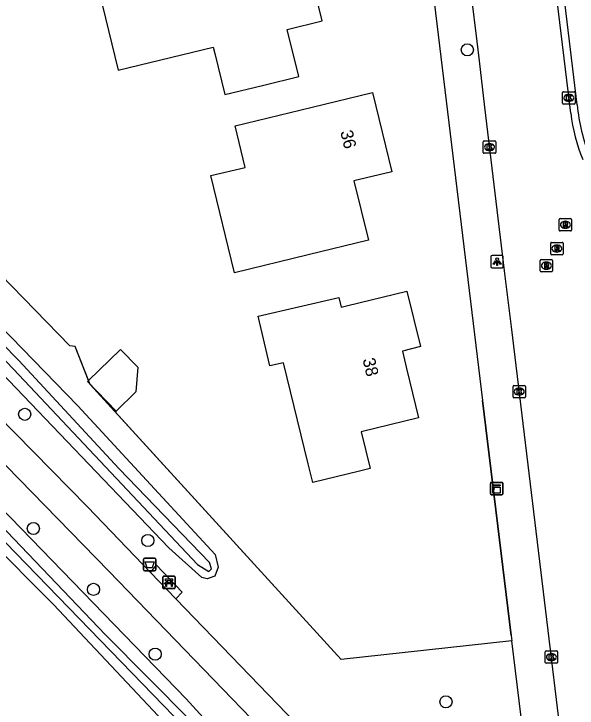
# Model space of a CAD drawing. Extents: x 157663 to 158496, y 379212 to 380934.
# Drawn here: x 158046.6 to 158091.9, y 380411.1 to 380467 of the extents above; entities that cross this region are included whole.
import ezdxf

# ---------------------------------------------------------------- set-up
doc = ezdxf.new("R2010")
doc.units = 0
for name, color, linetype in [('IMGEO_Afvalbak', 7, 'Continuous'), ('IMGEO_Bank', 7, 'Continuous'), ('IMGEO_Boom', 7, 'Continuous'), ('IMGEO_Groenvoorziening', 7, 'Continuous'), ('IMGEO_Hek', 7, 'Continuous'), ('IMGEO_Kast', 7, 'Continuous'), ('IMGEO_Kolk', 7, 'Continuous'), ('IMGEO_Lichtpunt', 7, 'Continuous'), ('IMGEO_Muur', 7, 'Continuous'), ('IMGEO_Pand', 7, 'Continuous'), ('IMGEO_Pand_nummerreeks', 7, 'Continuous'), ('IMGEO_Rijbaan_lokaal_open', 7, 'Continuous'), ('IMGEO_Rioolput', 7, 'Continuous'), ('IMGEO_Voetpad_open', 7, 'Continuous'), ('IMGEO_Waterloop', 7, 'Continuous')]:
    doc.layers.add(name, color=color, linetype=linetype)

msp = doc.modelspace()

# ---------------------------------------------------------------- linework, layer by layer
at = {"layer": 'IMGEO_Afvalbak'}
for p, q in [((158057.124, 380423.14), (158057.914, 380423.14)), ((158057.914, 380423.14), (158057.124, 380423.14)), ((158057.024, 380422.24), (158057.024, 380423.04)), ((158057.024, 380423.04), (158057.024, 380422.24)), ((158058.014, 380423.04), (158058.014, 380422.24)), ((158058.014, 380422.24), (158058.014, 380423.04)), ((158057.914, 380422.14), (158057.124, 380422.14)), ((158057.124, 380422.14), (158057.914, 380422.14))]:
    msp.add_line(p, q, dxfattribs=at)
msp.add_lwpolyline([(158057.167, 380422.854), (158057.871, 380422.854), (158057.722, 380422.384), (158057.316, 380422.384), (158057.167, 380422.854)], dxfattribs=at)
for centre, start, end in [((158057.124, 380423.04), 90, 180), ((158057.124, 380423.04), 90, 180), ((158057.914, 380423.04), 0, 90), ((158057.914, 380423.04), 360, 90), ((158057.124, 380422.24), 180, 270), ((158057.124, 380422.24), 180, 270), ((158057.914, 380422.24), 270, 0), ((158057.914, 380422.24), 270, 0)]:
    msp.add_arc(centre, 0.1, start, end, dxfattribs=at)
at = {"layer": 'IMGEO_Bank'}
for p, q in [((158058.579, 380420.771), (158058.579, 380421.612)), ((158058.579, 380421.612), (158058.579, 380420.771)), ((158058.654, 380421.696), (158059.495, 380421.696)), ((158059.495, 380421.696), (158058.654, 380421.696)), ((158059.579, 380421.621), (158059.579, 380420.78)), ((158059.579, 380420.78), (158059.579, 380421.621)), ((158059.276, 380421.094), (158058.883, 380421.094)), ((158058.888, 380421.202), (158058.888, 380421.308)), ((158058.932, 380421.308), (158058.932, 380421.202)), ((158059.22, 380421.314), (158058.938, 380421.314)), ((158058.938, 380421.196), (158059.22, 380421.196)), ((158059.226, 380421.202), (158059.226, 380421.308)), ((158059.27, 380421.308), (158059.27, 380421.202)), ((158059.504, 380420.696), (158058.663, 380420.696)), ((158058.663, 380420.696), (158059.504, 380420.696))]:
    msp.add_line(p, q, dxfattribs=at)
for points in [[(158058.882, 380421.314), (158058.796, 380421.314), (158058.796, 380421.475), (158059.359, 380421.475), (158059.359, 380421.314), (158059.276, 380421.314)], [(158058.826, 380421.094), (158058.684, 380421.094), (158058.796, 380421.196), (158058.882, 380421.196)], [(158058.876, 380421.087), (158058.876, 380420.88), (158058.833, 380420.88), (158058.833, 380421.087)], [(158059.276, 380421.196), (158059.359, 380421.196), (158059.471, 380421.094), (158059.332, 380421.094)], [(158059.326, 380421.087), (158059.326, 380420.88), (158059.282, 380420.88), (158059.282, 380421.087)]]:
    msp.add_lwpolyline(points, dxfattribs=at)
for centre, radius, start, end in [((158058.657, 380421.618), 0.0779, 92.4484, 184.2845), ((158058.657, 380421.618), 0.0779, 92.4484, 184.2845), ((158059.501, 380421.618), 0.0779, 2.4484, 94.2845), ((158059.501, 380421.618), 0.0779, 2.4484, 94.2845), ((158058.826, 380421.087), 0.00671, 2.8957, 87.1043), ((158058.883, 380421.087), 0.00671, 92.8957, 177.1043), ((158058.881, 380421.307), 0.00671, 2.8957, 87.1043), ((158058.881, 380421.203), 0.00671, 272.8957, 357.1043), ((158058.938, 380421.307), 0.00671, 92.8957, 177.1043), ((158058.938, 380421.203), 0.00671, 182.8957, 267.1043), ((158059.22, 380421.307), 0.00671, 2.8957, 87.1043), ((158059.22, 380421.203), 0.00671, 272.8957, 357.1043), ((158059.277, 380421.307), 0.00671, 92.8957, 177.1043), ((158059.277, 380421.203), 0.00671, 182.8957, 267.1043), ((158059.275, 380421.087), 0.00671, 2.8957, 87.1043), ((158059.332, 380421.087), 0.00671, 92.8957, 177.1043), ((158058.657, 380420.774), 0.0779, 182.4484, 274.2845), ((158058.657, 380420.774), 0.0779, 182.4484, 274.2845), ((158059.501, 380420.774), 0.0779, 272.4484, 4.2845), ((158059.501, 380420.774), 0.0779, 272.4484, 4.2845)]:
    msp.add_arc(centre, radius, start, end, dxfattribs=at)
at = {"layer": 'IMGEO_Boom'}
for centre in [(158083.093, 380464.08), (158047.463, 380434.732), (158048.159, 380425.543), (158057.379, 380424.579), (158053.003, 380420.637), (158057.961, 380415.427), (158081.373, 380411.578)]:
    msp.add_circle(centre, 0.489, dxfattribs=at)
at = {"layer": 'IMGEO_Groenvoorziening'}
for points in [[(158051.734, 380435.421), (158062.804, 380423.435), (158063.034, 380422.418), (158062.773, 380421.709), (158062.142, 380421.478), (158061.715, 380421.586), (158059.072, 380423.978), (158035.643, 380448.459), (158025.607, 380458.749), (158024.421, 380460.97), (158024.539, 380461.599), (158024.891, 380461.928), (158025.703, 380461.837), (158026.714, 380461.388), (158035.627, 380451.982), (158051.734, 380435.421)], [(158021.901, 380448.106), (158021.75, 380448.847), (158021.75, 380449.873), (158021.907, 380450.575), (158022.246, 380450.981), (158022.582, 380450.916), (158024.971, 380448.209), (158041.314, 380431.54), (158060.467, 380411.817), (158064.837, 380407.009)], [(158052.599, 380437.464), (158051.524, 380440.195), (158051.082, 380440.247), (158042.683, 380448.851), (158042.449, 380449.52)], [(158021.901, 380448.106), (158022.644, 380447.175), (158033.581, 380435.679), (158049.766, 380419.415), (158061.595, 380406.859), (158064.13, 380404.829), (158064.886, 380404.754), (158065.351, 380405.014), (158065.528, 380405.554), (158064.837, 380407.009)], [(158086.681, 380416.507), (158072.931, 380414.996), (158054.747, 380434.921), (158054.814, 380434.985)]]:
    msp.add_lwpolyline(points, dxfattribs=at)
at = {"layer": 'IMGEO_Hek'}
msp.add_lwpolyline([(158086.631, 380416.924), (158084.325, 380435.852)], dxfattribs=at)
at = {"layer": 'IMGEO_Kast'}
for p, q in [((158084.951, 380428.33), (158084.951, 380429.171)), ((158084.951, 380429.171), (158084.951, 380428.33)), ((158085.026, 380429.255), (158085.867, 380429.255)), ((158085.867, 380429.255), (158085.026, 380429.255)), ((158085.951, 380429.18), (158085.951, 380428.339)), ((158085.951, 380428.339), (158085.951, 380429.18)), ((158085.876, 380428.255), (158085.035, 380428.255)), ((158085.035, 380428.255), (158085.876, 380428.255))]:
    msp.add_line(p, q, dxfattribs=at)
for points in [[(158085.146, 380429.045), (158085.746, 380429.045), (158085.746, 380428.96), (158085.146, 380428.96), (158085.146, 380429.045)], [(158085.146, 380428.87), (158085.746, 380428.87), (158085.746, 380428.381), (158085.146, 380428.381), (158085.146, 380428.87)]]:
    msp.add_lwpolyline(points, dxfattribs=at)
msp.add_circle((158085.23, 380428.719), 0.0377, dxfattribs=at)
for centre, start, end in [((158085.029, 380429.177), 92.4484, 184.2845), ((158085.029, 380429.177), 92.4484, 184.2845), ((158085.873, 380429.177), 2.4484, 94.2845), ((158085.873, 380429.177), 2.4484, 94.2845), ((158085.029, 380428.333), 182.4484, 274.2845), ((158085.029, 380428.333), 182.4484, 274.2845), ((158085.873, 380428.333), 272.4484, 4.2845), ((158085.873, 380428.333), 272.4484, 4.2845)]:
    msp.add_arc(centre, 0.0779, start, end, dxfattribs=at)
at = {"layer": 'IMGEO_Kolk'}
for p, q in [((158090.762, 380459.776), (158090.762, 380460.628)), ((158090.837, 380460.702), (158091.689, 380460.702)), ((158091.763, 380460.628), (158091.763, 380459.776)), ((158091.25, 380460.482), (158091.275, 380460.482)), ((158091.689, 380459.702), (158090.837, 380459.702)), ((158091.273, 380459.922), (158091.248, 380459.922)), ((158084.378, 380455.82), (158084.378, 380456.672)), ((158084.453, 380456.746), (158085.305, 380456.746)), ((158085.379, 380456.672), (158085.379, 380455.82)), ((158084.866, 380456.526), (158084.891, 380456.526)), ((158085.305, 380455.746), (158084.453, 380455.746)), ((158084.889, 380455.966), (158084.864, 380455.966)), ((158086.772, 380436.131), (158086.772, 380436.983)), ((158086.847, 380437.057), (158087.699, 380437.057)), ((158087.26, 380436.837), (158087.285, 380436.837)), ((158087.773, 380436.983), (158087.773, 380436.131)), ((158087.699, 380436.057), (158086.847, 380436.057)), ((158087.283, 380436.277), (158087.258, 380436.277)), ((158089.361, 380414.763), (158089.361, 380415.615)), ((158089.436, 380415.689), (158090.288, 380415.689)), ((158089.849, 380415.469), (158089.874, 380415.469)), ((158090.362, 380415.615), (158090.362, 380414.763)), ((158089.872, 380414.909), (158089.847, 380414.909)), ((158090.288, 380414.689), (158089.436, 380414.689))]:
    msp.add_line(p, q, dxfattribs=at)
for points in [[(158090.762, 380459.776), (158090.762, 380460.628)], [(158090.837, 380460.702), (158091.689, 380460.702)], [(158091.763, 380460.628), (158091.763, 380459.776)], [(158091.083, 380460.402), (158091.206, 380460.402), (158091.206, 380460.251), (158091.336, 380460.402), (158091.5, 380460.402), (158091.354, 380460.251), (158091.507, 380460.002), (158091.355, 380460.002), (158091.27, 380460.166), (158091.206, 380460.099), (158091.206, 380460.002), (158091.083, 380460.002), (158091.083, 380460.402)], [(158091.689, 380459.702), (158090.837, 380459.702)], [(158084.378, 380455.82), (158084.378, 380456.672)], [(158084.453, 380456.746), (158085.305, 380456.746)], [(158085.379, 380456.672), (158085.379, 380455.82)], [(158084.699, 380456.446), (158084.822, 380456.446), (158084.822, 380456.295), (158084.952, 380456.446), (158085.116, 380456.446), (158084.97, 380456.295), (158085.123, 380456.046), (158084.971, 380456.046), (158084.886, 380456.21), (158084.822, 380456.143), (158084.822, 380456.046), (158084.699, 380456.046), (158084.699, 380456.446)], [(158085.305, 380455.746), (158084.453, 380455.746)], [(158086.772, 380436.131), (158086.772, 380436.983)], [(158086.847, 380437.057), (158087.699, 380437.057)], [(158087.093, 380436.757), (158087.216, 380436.757), (158087.216, 380436.606), (158087.346, 380436.757), (158087.51, 380436.757), (158087.364, 380436.606), (158087.517, 380436.357), (158087.365, 380436.357), (158087.28, 380436.521), (158087.216, 380436.454), (158087.216, 380436.357), (158087.093, 380436.357), (158087.093, 380436.757)], [(158087.773, 380436.983), (158087.773, 380436.131)], [(158087.699, 380436.057), (158086.847, 380436.057)], [(158089.361, 380414.763), (158089.361, 380415.615)], [(158089.436, 380415.689), (158090.288, 380415.689)], [(158089.682, 380415.389), (158089.805, 380415.389), (158089.805, 380415.238), (158089.935, 380415.389), (158090.099, 380415.389), (158089.953, 380415.238), (158090.106, 380414.989), (158089.954, 380414.989), (158089.869, 380415.153), (158089.805, 380415.086), (158089.805, 380414.989), (158089.682, 380414.989), (158089.682, 380415.389)], [(158090.362, 380415.615), (158090.362, 380414.763)], [(158090.288, 380414.689), (158089.436, 380414.689)]]:
    msp.add_lwpolyline(points, dxfattribs=at)
for centre, start, end in [((158090.839, 380460.626), 91.552, 178.448), ((158090.839, 380460.626), 91.552, 178.448), ((158091.687, 380460.626), 1.552, 88.448), ((158091.687, 380460.626), 1.552, 88.448), ((158090.839, 380459.778), 181.552, 268.448), ((158090.839, 380459.778), 181.552, 268.448), ((158091.687, 380459.778), 271.552, 358.448), ((158091.687, 380459.778), 271.552, 358.448), ((158084.455, 380456.67), 91.552, 178.448), ((158084.455, 380456.67), 91.552, 178.448), ((158085.303, 380456.67), 1.552, 88.448), ((158085.303, 380456.67), 1.552, 88.448), ((158084.455, 380455.822), 181.552, 268.448), ((158084.455, 380455.822), 181.552, 268.448), ((158085.303, 380455.822), 271.552, 358.448), ((158085.303, 380455.822), 271.552, 358.448), ((158086.849, 380436.981), 91.552, 178.448), ((158086.849, 380436.981), 91.552, 178.448), ((158087.697, 380436.981), 1.552, 88.448), ((158087.697, 380436.981), 1.552, 88.448), ((158086.849, 380436.133), 181.552, 268.448), ((158086.849, 380436.133), 181.552, 268.448), ((158087.697, 380436.133), 271.552, 358.448), ((158087.697, 380436.133), 271.552, 358.448), ((158089.438, 380415.613), 91.552, 178.448), ((158089.438, 380415.613), 91.552, 178.448), ((158090.286, 380415.613), 1.552, 88.448), ((158090.286, 380415.613), 1.552, 88.448), ((158089.438, 380414.765), 181.552, 268.448), ((158089.438, 380414.765), 181.552, 268.448), ((158090.286, 380414.765), 271.552, 358.448), ((158090.286, 380414.765), 271.552, 358.448)]:
    msp.add_arc(centre, 0.0765, start, end, dxfattribs=at)
for centre, major_axis, ratio, start_param, end_param in [((158091.249, 380460.202), (-0.387, 0.002), 0.722429, 4.712389, 7.853982), ((158091.274, 380460.202), (-0.39, 0.002), 0.717154, 1.570796, 4.712389), ((158084.865, 380456.246), (-0.387, 0.002), 0.722429, 4.712389, 7.853982), ((158084.89, 380456.246), (-0.39, 0.002), 0.717154, 1.570796, 4.712389), ((158087.259, 380436.557), (-0.387, 0.002), 0.722429, 4.712389, 7.853982), ((158087.284, 380436.557), (-0.39, 0.002), 0.717154, 1.570796, 4.712389), ((158089.848, 380415.189), (-0.387, 0.002), 0.722429, 4.712389, 7.853982), ((158089.873, 380415.189), (-0.39, 0.002), 0.717154, 1.570796, 4.712389)]:
    msp.add_ellipse(centre, major_axis=major_axis, ratio=ratio, start_param=start_param, end_param=end_param, dxfattribs=at)
at = {"layer": 'IMGEO_Lichtpunt'}
for p, q in [((158084.994, 380447.425), (158084.994, 380446.618)), ((158084.994, 380447.425), (158084.994, 380446.618)), ((158085.896, 380447.52), (158085.088, 380447.52)), ((158085.896, 380447.52), (158085.088, 380447.52)), ((158085.99, 380446.618), (158085.99, 380447.425)), ((158085.99, 380446.618), (158085.99, 380447.425)), ((158085.088, 380446.524), (158085.896, 380446.524)), ((158085.088, 380446.524), (158085.896, 380446.524))]:
    msp.add_line(p, q, dxfattribs=at)
for points in [[(158085.368, 380447.089), (158085.407, 380447.061), (158085.219, 380446.799), (158085.181, 380446.826), (158085.368, 380447.089)], [(158085.47, 380447.041), (158085.517, 380447.041), (158085.517, 380446.719), (158085.47, 380446.719), (158085.47, 380447.041)], [(158085.58, 380447.061), (158085.618, 380447.088), (158085.805, 380446.826), (158085.766, 380446.798), (158085.58, 380447.061)]]:
    msp.add_lwpolyline(points, dxfattribs=at)
msp.add_circle((158085.493, 380447.223), 0.0994, dxfattribs=at)
for centre, start, end in [((158085.088, 380447.425), 90, 180), ((158085.088, 380447.425), 90, 180), ((158085.896, 380447.425), 0, 90), ((158085.896, 380447.425), 0, 90), ((158085.088, 380446.618), 180, 270), ((158085.088, 380446.618), 180, 270), ((158085.896, 380446.618), 270, 0), ((158085.896, 380446.618), 270, 360)]:
    msp.add_arc(centre, 0.0946, start, end, dxfattribs=at)
at = {"layer": 'IMGEO_Muur'}
msp.add_lwpolyline([(158086.681, 380416.507), (158072.931, 380414.996), (158052.73, 380437.131), (158051.524, 380440.195), (158051.082, 380440.247), (158042.683, 380448.851), (158041.604, 380451.94), (158040.592, 380455.178), (158036.537, 380455.559), (158031.471, 380460.739), (158027.482, 380465.252)], dxfattribs=at)
at = {"layer": 'IMGEO_Pand'}
for points in [[(158070.106, 380471.734), (158071.817, 380472.15), (158071.25, 380474.483), (158072.233, 380474.722), (158071.005, 380479.768), (158066.147, 380478.586), (158061.551, 380477.468), (158054.903, 380475.85), (158051.903, 380475.12), (158054.99, 380462.43), (158062.63, 380464.289), (158062.754, 380463.778), (158063.559, 380460.468), (158066.712, 380461.235), (158069.52, 380461.918), (158068.595, 380465.717), (158071.403, 380466.4), (158070.106, 380471.734)], [(158075.466, 380460.64), (158077.019, 380454.259), (158073.968, 380453.517), (158075.127, 380448.751), (158070.269, 380447.569), (158064.353, 380446.13), (158062.452, 380453.944), (158065.202, 380454.613), (158064.391, 380457.946), (158070.608, 380459.458), (158075.466, 380460.64)], [(158079.312, 380440.181), (158077.863, 380439.828), (158078.208, 380438.411), (158079.172, 380434.446), (158074.552, 380433.322), (158075.272, 380430.36), (158074.403, 380430.148), (158070.649, 380429.234), (158070.279, 380430.753), (158068.303, 380438.877), (158067.2, 380438.622), (158066.266, 380442.629), (158072.761, 380444.144), (158072.95, 380443.368), (158073.366, 380443.469), (158078.224, 380444.651), (158079.312, 380440.181)], [(158052.599, 380437.464), (158055.179, 380439.953), (158056.556, 380438.526), (158056.415, 380436.528), (158054.814, 380434.985)], [(158054.814, 380434.985), (158052.508, 380437.376), (158052.599, 380437.464)]]:
    msp.add_lwpolyline(points, dxfattribs=at)
at = {"layer": 'IMGEO_Rijbaan_lokaal_open'}
for points in [[(158091.416, 380458.976), (158090.221, 380468.97), (158089.784, 380472.738), (158088.547, 380482.967), (158088.09, 380486.736), (158086.903, 380496.686), (158086.439, 380500.445), (158085.198, 380510.659), (158084.741, 380514.431), (158082.958, 380529.523)], [(158091.201, 380403.997), (158086.642, 380441.77), (158086.089, 380446.282), (158084.501, 380459.454), (158084.064, 380463.2), (158083.878, 380464.74), (158083.435, 380468.487), (158082.23, 380478.604), (158081.782, 380482.399), (158080.477, 380493.331), (158079.926, 380497.842), (158078.254, 380511.803), (158077.715, 380516.353), (158076.245, 380528.73)]]:
    msp.add_lwpolyline(points, dxfattribs=at)
msp.add_arc((158106.334, 380460.847), 15.035, 187.1492, 201.909, dxfattribs=at)
at = {"layer": 'IMGEO_Rioolput'}
for p, q in [((158090.484, 380449.567), (158090.484, 380450.419)), ((158090.559, 380450.493), (158091.411, 380450.493)), ((158090.972, 380450.273), (158090.997, 380450.273)), ((158091.485, 380450.419), (158091.485, 380449.567)), ((158091.411, 380449.493), (158090.559, 380449.493)), ((158090.995, 380449.713), (158090.97, 380449.713)), ((158089.803, 380447.649), (158089.803, 380448.501)), ((158089.878, 380448.575), (158090.73, 380448.575)), ((158090.291, 380448.355), (158090.316, 380448.355)), ((158090.804, 380448.501), (158090.804, 380447.649)), ((158090.314, 380447.795), (158090.289, 380447.795)), ((158089.031, 380447.199), (158089.883, 380447.199)), ((158090.73, 380447.575), (158089.878, 380447.575)), ((158088.956, 380446.273), (158088.956, 380447.125)), ((158089.444, 380446.979), (158089.469, 380446.979)), ((158089.957, 380447.125), (158089.957, 380446.273)), ((158089.883, 380446.199), (158089.031, 380446.199)), ((158089.467, 380446.419), (158089.442, 380446.419))]:
    msp.add_line(p, q, dxfattribs=at)
for points in [[(158090.484, 380449.567), (158090.484, 380450.419)], [(158090.559, 380450.493), (158091.411, 380450.493)], [(158091.073, 380450.191), (158090.821, 380450.193), (158090.821, 380449.793)], [(158090.999, 380450.112), (158090.945, 380450.112), (158090.945, 380450.031)], [(158090.945, 380450.031), (158090.997, 380450.031)], [(158091.485, 380450.419), (158091.485, 380449.567)], [(158091.411, 380449.493), (158090.559, 380449.493)], [(158090.821, 380449.793), (158090.945, 380449.793), (158090.945, 380449.955), (158090.956, 380449.955)], [(158091.003, 380449.926), (158091.074, 380449.793), (158091.214, 380449.793), (158091.149, 380449.919)], [(158089.803, 380447.649), (158089.803, 380448.501)], [(158089.878, 380448.575), (158090.73, 380448.575)], [(158090.804, 380448.501), (158090.804, 380447.649)], [(158090.392, 380448.273), (158090.14, 380448.275), (158090.14, 380447.875)], [(158090.14, 380447.875), (158090.264, 380447.875), (158090.264, 380448.037), (158090.275, 380448.037)], [(158090.318, 380448.194), (158090.264, 380448.194), (158090.264, 380448.113)], [(158090.264, 380448.113), (158090.316, 380448.113)], [(158090.322, 380448.008), (158090.393, 380447.875), (158090.533, 380447.875), (158090.468, 380448.001)], [(158089.031, 380447.199), (158089.883, 380447.199)], [(158090.73, 380447.575), (158089.878, 380447.575)], [(158088.956, 380446.273), (158088.956, 380447.125)], [(158089.545, 380446.897), (158089.293, 380446.899), (158089.293, 380446.499)], [(158089.293, 380446.499), (158089.417, 380446.499), (158089.417, 380446.661), (158089.428, 380446.661)], [(158089.471, 380446.818), (158089.417, 380446.818), (158089.417, 380446.737)], [(158089.417, 380446.737), (158089.469, 380446.737)], [(158089.475, 380446.632), (158089.546, 380446.499), (158089.686, 380446.499), (158089.621, 380446.625)], [(158089.957, 380447.125), (158089.957, 380446.273)], [(158089.883, 380446.199), (158089.031, 380446.199)]]:
    msp.add_lwpolyline(points, dxfattribs=at)
for centre, radius, start, end in [((158090.561, 380450.417), 0.0765, 91.552, 178.448), ((158090.561, 380450.417), 0.0765, 91.552, 178.448), ((158090.981, 380450.22), 0.19, 274.7715, 282.9687), ((158091.005, 380450.016), 0.0964, 77.0061, 93.1865), ((158091.019, 380450.073), 0.0378, 276.6634, 79.6772), ((158091.072, 380450.081), 0.109, 350.3612, 89.416), ((158091.07, 380450.081), 0.112, 277.5842, 350.9817), ((158091.054, 380449.866), 0.108, 29.5134, 73.7905), ((158091.409, 380450.417), 0.0765, 1.552, 88.448), ((158091.409, 380450.417), 0.0765, 1.552, 88.448), ((158090.561, 380449.569), 0.0765, 181.552, 268.448), ((158090.561, 380449.569), 0.0765, 181.552, 268.448), ((158090.955, 380449.902), 0.0533, 26.0293, 88.6989), ((158091.409, 380449.569), 0.0765, 271.552, 358.448), ((158091.409, 380449.569), 0.0765, 271.552, 358.448), ((158089.88, 380448.499), 0.0765, 91.552, 178.448), ((158089.88, 380448.499), 0.0765, 91.552, 178.448), ((158090.728, 380448.499), 0.0765, 1.552, 88.448), ((158090.728, 380448.499), 0.0765, 1.552, 88.448), ((158090.274, 380447.984), 0.0533, 26.0293, 88.6989), ((158090.3, 380448.302), 0.19, 274.7715, 282.9687), ((158090.324, 380448.098), 0.0964, 77.0061, 93.1865), ((158090.338, 380448.155), 0.0378, 276.6634, 79.6772), ((158090.391, 380448.163), 0.109, 350.3612, 89.416), ((158090.389, 380448.163), 0.112, 277.5842, 350.9817), ((158090.373, 380447.948), 0.108, 29.5134, 73.7905), ((158089.033, 380447.123), 0.0765, 91.552, 178.448), ((158089.033, 380447.123), 0.0765, 91.552, 178.448), ((158089.88, 380447.651), 0.0765, 181.552, 268.448), ((158089.88, 380447.651), 0.0765, 181.552, 268.448), ((158089.881, 380447.123), 0.0765, 1.552, 88.448), ((158089.881, 380447.123), 0.0765, 1.552, 88.448), ((158090.728, 380447.651), 0.0765, 271.552, 358.448), ((158090.728, 380447.651), 0.0765, 271.552, 358.448), ((158089.427, 380446.608), 0.0533, 26.0293, 88.6989), ((158089.453, 380446.926), 0.19, 274.7715, 282.9687), ((158089.477, 380446.722), 0.0964, 77.0061, 93.1865), ((158089.491, 380446.779), 0.0378, 276.6634, 79.6772), ((158089.544, 380446.787), 0.109, 350.3612, 89.416), ((158089.542, 380446.787), 0.112, 277.5842, 350.9817), ((158089.526, 380446.572), 0.108, 29.5134, 73.7905), ((158089.033, 380446.275), 0.0765, 181.552, 268.448), ((158089.033, 380446.275), 0.0765, 181.552, 268.448), ((158089.881, 380446.275), 0.0765, 271.552, 358.448), ((158089.881, 380446.275), 0.0765, 271.552, 358.448)]:
    msp.add_arc(centre, radius, start, end, dxfattribs=at)
for centre, major_axis, ratio, start_param, end_param in [((158090.971, 380449.993), (-0.387, 0.002), 0.722429, 4.712389, 7.853982), ((158090.996, 380449.993), (-0.39, 0.002), 0.717154, 1.570796, 4.712389), ((158090.29, 380448.075), (-0.387, 0.002), 0.722429, 4.712389, 7.853982), ((158090.315, 380448.075), (-0.39, 0.002), 0.717154, 1.570796, 4.712389), ((158089.443, 380446.699), (-0.387, 0.002), 0.722429, 4.712389, 7.853982), ((158089.468, 380446.699), (-0.39, 0.002), 0.717154, 1.570796, 4.712389)]:
    msp.add_ellipse(centre, major_axis=major_axis, ratio=ratio, start_param=start_param, end_param=end_param, dxfattribs=at)
at = {"layer": 'IMGEO_Voetpad_open'}
for points in [[(158018.553, 380541.968), (158017.655, 380538.691), (158016.922, 380535.577), (158016.38, 380532.759), (158016.054, 380527.981), (158016.232, 380525.978), (158017.441, 380518.75), (158020.768, 380504.58), (158024.596, 380487.672), (158027.158, 380477.899), (158027.35, 380476.128), (158027.219, 380474.599), (158026.944, 380473.412), (158026.295, 380471.968), (158024.419, 380469.661), (158023.371, 380468.153), (158021.162, 380465.935), (158022.423, 380454.718), (158023.317, 380453.788), (158054.227, 380422.099), (158074.872, 380400.738)], [(158020.283, 380541.51), (158019.068, 380536.629), (158018.258, 380532.115), (158018.049, 380530.053), (158018.149, 380525.829), (158018.371, 380523.767), (158019.073, 380520.078), (158026.659, 380487.511), (158029.27, 380477.483), (158029.675, 380474.657), (158029.439, 380473.013), (158029.089, 380471.859), (158024.22, 380466.173), (158023.153, 380465.044), (158024.181, 380456.051), (158024.539, 380455.555), (158033.6, 380446.522), (158052.528, 380427.284), (158057.599, 380421.983)], [(158091.931, 380459.649), (158084.108, 380524.698), (158083.47, 380530.375)], [(158074.678, 380515.405), (158076.753, 380498.285), (158084.325, 380435.852), (158086.631, 380416.924), (158086.681, 380416.507)], [(158057.599, 380421.983), (158058.058, 380422.588), (158060.148, 380420.401), (158059.616, 380419.875)], [(158059.616, 380419.875), (158057.599, 380421.983)], [(158059.616, 380419.875), (158077.461, 380401.381), (158087.42, 380410.342)], [(158087.42, 380410.342), (158086.681, 380416.507)]]:
    msp.add_lwpolyline(points, dxfattribs=at)
msp.add_arc((158107.332, 380461.195), 15.479, 185.7315, 201.6945, dxfattribs=at)
at = {"layer": 'IMGEO_Waterloop'}
for points in [[(158062.279, 380422.071), (158062.49, 380422.283), (158062.337, 380422.808), (158055.05, 380430.381), (158046.996, 380439.074), (158038.697, 380447.499), (158025.979, 380461.024), (158025.52, 380461.021), (158025.219, 380460.787), (158025.425, 380460.301), (158029.37, 380456.336), (158046.551, 380438.375), (158061.372, 380422.653), (158062.279, 380422.071)], [(158064.485, 380406.114), (158064.222, 380406.634), (158053.964, 380416.969), (158041.488, 380430.009), (158030.525, 380441.266), (158023.618, 380448.807), (158022.695, 380449.655), (158022.445, 380449.67), (158022.286, 380449.523), (158022.313, 380449.025), (158022.558, 380448.594), (158038.281, 380432.283), (158063.717, 380406.06), (158064.31, 380405.941), (158064.485, 380406.114)]]:
    msp.add_lwpolyline(points, dxfattribs=at)

# ---------------------------------------------------------------- texts
at = {"layer": 'IMGEO_Pand_nummerreeks'}
for s, rotation, p in [('36', 283.6763, (158072.86, 380457.477)), ('38', 283.682, (158074.654, 380439.143))]:
    msp.add_text(s, height=1, rotation=rotation, dxfattribs=at).set_placement(p)

doc.saveas('drawing.dxf')
